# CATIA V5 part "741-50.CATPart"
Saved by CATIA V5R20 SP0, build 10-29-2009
Part number: 741-50
Bounding box of the stored display mesh (mm): x -40 to 40, y -40 to 40, z -47 to 50
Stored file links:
  C:\Users\Utente\Desktop\IO LAVORO\3D X SITO CF\X SITO\741\741-50.CATPart
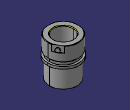
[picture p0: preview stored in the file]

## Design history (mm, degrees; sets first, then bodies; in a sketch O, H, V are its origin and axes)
Set1
  DatumSurface1 to DatumSurface42 "741-50"
Body1 (main body)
